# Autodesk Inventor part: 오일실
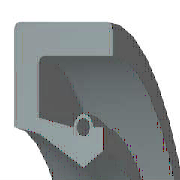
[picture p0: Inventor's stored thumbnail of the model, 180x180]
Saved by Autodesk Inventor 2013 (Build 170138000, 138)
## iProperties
IsCustomPart: 1
Created: 2009-02
Part Number: 오일실
Material: 고무
Description: 오일-실
Document SubType Name: Modeling
Standard: KS B 2804
Designer: SeoGD™[esajin.kr]
Standards Organization: KS
Language: ko-KR
Size Designation: S - 25 38 8
Categories: <MemberInstance><Categories><Category DisplayName="샤프트 부품" InternalName="7f7aeb1f-a693-4053-b835-cee3144e0d98" Mnemonic="SHFT"><Category DisplayName="실링" Intern
Density: 0.93 g/cm^3
Mass: 2.23721 g
Surface Area: 37.0166 cm^2
Volume: 2.4056 cm^3
Author: SeoGD™[esajin.kr]
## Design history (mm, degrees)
revolve "본체" stored, may be unused: angle "d17" = 90 deg
revolve "스프링1" stored, may be unused: angle "d18" = 90 deg
body "Solid1"
sketch "스케치1"
  geometry: L1 (0, 19)-(8, 19); L2 (8, 19)-(8, 17.75); L3 (8, 17.75)-(1.75, 17.75); L4 (0, 19)-(0, 14.6); L5 (0, 14.6)-(1.75, 14.25); L6 (1.75, 14.25)-(4.9, 12.5); L7 (4.9, 12.5)-(0, 12.5); L8 (6.3, 13.375)-(6.3, 14.6); L9 (0, 0)-(9.586, 0) reference; L10 (4.9, 12.5)-(6.3, 13.375); L11 (0, 18)-(0, -3) reference; L12 (-1.917, 0)-(11.503, 0) reference; L13 (4.2, 14.6)-(1.75, 15.09); L14 (1.75, 15.09)-(1.75, 17.75); L15 (6.3, 14.6)-(5.6, 14.6); C1 r 0.455 at (4.9, 14.6); A1 r 0.7 centre (4.9, 14.6) between (5.6, 14.6) and (4.2, 14.6)
  constraints: 26 end point, 5 horizontal alignment, 4 perpendicular, 2 centre point, 2 collinear, 2 horizontal, 2 parallel, 2 point on circle, 2 point on line, 2 vertical alignment, 1 coincident
  dimensions: "d0" = 38 diameter of L1 L9 (= SD2); "d1" = 26.75 diameter of L8.start L9 (= ABDM); "d2" = 1.25 distance of L1.end L2.end (computed from SD); "d3" = 0.91 diameter of C1 (= SPDI); "d4" = 1.4 diameter of A1 (= SPDA); "d5" = 25 diameter of L6.end L9 (= NND); "d6" = 28.5 diameter of L5.end L9 (= TKDM); "d7" = 29.2 diameter of L4.end L9 (= HLDM); "d8" = 4.9 distance from line of C1.centre L4 (= SPDST); "d9" = 6.3 distance between parallel lines of L8 L4 (= SDI); "d10" = 8 distance between parallel lines of L2 L4 (= SWDT); "d12" = 1.75 distance between parallel lines of L14 L4 (= SD)
fillet "모깎기1" dims "d11" = 0.3 (= RR)
other parameters: "SD2" = 38 [user parameter; used in 1 equation term], "SWDT" = 8 [user parameter; used in 1 equation term], "RR" = 0.3 [user parameter; used in 1 equation term], "SD" = 1.75 [user parameter; used in 2 equation terms], "NND" = 25 [user parameter; used in 1 equation term], "SPDA" = 1.4 [user parameter; used in 1 equation term], "SPDI" = 0.91 [user parameter; used in 1 equation term], "TKDM" = 28.5 [user parameter; used in 1 equation term], "HLDM" = 29.2 [user parameter; used in 1 equation term], "ABDM" = 26.75 [user parameter; used in 1 equation term], "SDI" = 6.3 [user parameter; used in 1 equation term], "SPDST" = 4.9 [user parameter; used in 1 equation term], "d13" = 0, "d14" = 0, "d15" = 0, "LAB" = 0.35 [user parameter]
